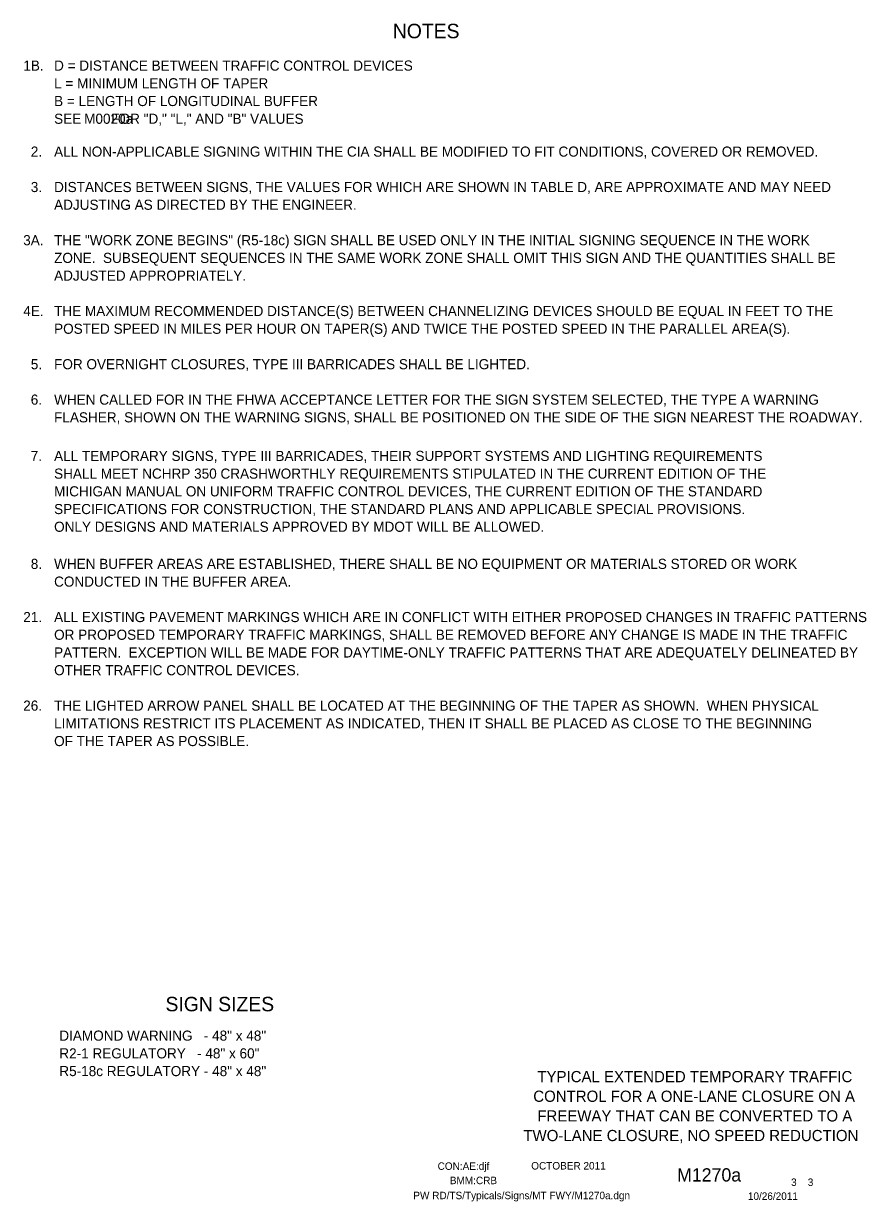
# Model space of a CAD drawing. Extents: x 16794 to 19504, y 7009 to 8243.
# Drawn here: x 18805 to 19504, y 7218 to 8195 of the extents above; entities that cross this region are included whole.
import ezdxf

# ---------------------------------------------------------------- set-up
doc = ezdxf.new("R2010")
doc.units = 0
for name, color, linetype in [('BORDER', 7, 'Continuous'), ('BORDER_SIGNAL_WO', 7, 'Continuous'), ('TYPICAL_TEXT_DIMEN_PR', 7, 'Continuous')]:
    doc.layers.add(name, color=color, linetype=linetype)

msp = doc.modelspace()

# ---------------------------------------------------------------- linework, layer by layer
at = {"layer": 'BORDER'}
msp.add_line((19347.25, 7297.5), (19347.25, 7297.5), dxfattribs=at)
msp.add_line((19347.25, 7297.5), (19347.25, 7297.5), dxfattribs=at)

# ---------------------------------------------------------------- texts
for s, p in [('TYPICAL EXTENDED TEMPORARY TRAFFIC', (19231.38, 7317.03)), ('CONTROL FOR A ONE-LANE CLOSURE ON A', (19228, 7300.73)), ('FREEWAY THAT CAN BE CONVERTED TO A', (19231.33, 7284.43)), ('TWO-LANE CLOSURE, NO SPEED REDUCTION ', (19219.79, 7268.13))]:
    msp.add_text(s, height=9.3, dxfattribs=at).set_placement(p)
at = {"layer": 'BORDER_SIGNAL_WO'}
for s, height, p in [('CON:AE:djf  ', 6.2, (19148.69, 7244.31)), ('    OCTOBER 2011    ', 6.2, (19217.08, 7244.59)), ('    M1270a   ', 11, (19330.86, 7234.63)), ('BMM:CRB   ', 6.2, (19158.81, 7232.42)), (' 3    3 ', 6.2, (19439.45, 7230.95)), ('PW RD/TS/Typicals/Signs/MT FWY/M1270a.dgn      ', 6.2, (19128.55, 7219.96)), ('10/26/2011    ', 6.2, (19405.93, 7219.38))]:
    msp.add_text(s, height=height, dxfattribs=at).set_placement(p)
at = {"layer": 'TYPICAL_TEXT_DIMEN_PR'}
for s, height, p in [('NOTES', 12, (19111.55, 8183.25)), ('1B.', 8.4, (18805.19, 8156.36)), ('D = DISTANCE BETWEEN TRAFFIC CONTROL DEVICES', 8.4, (18830.7, 8156.36)), ('L = MINIMUM LENGTH OF TAPER', 8.4, (18830.7, 8141.66)), ('B = LENGTH OF LONGITUDINAL BUFFER', 8.4, (18830.7, 8126.96)), ('SEE        FOR "D," "L," AND "B" VALUES', 8.4, (18830.7, 8112.26)), ('M0020a', 8.4, (18855.62, 8112.26)), ('2.', 8.4, (18811.39, 8085)), ('ALL NON-APPLICABLE SIGNING WITHIN THE CIA SHALL BE MODIFIED TO FIT CONDITIONS, COVERED OR REMOVED.', 8.4, (18830.7, 8085)), ('3.', 8.4, (18811.39, 8055.6)), ('DISTANCES BETWEEN SIGNS, THE VALUES FOR WHICH ARE SHOWN IN TABLE D, ARE APPROXIMATE AND MAY NEED', 8.4, (18830.7, 8055.6)), ('ADJUSTING AS DIRECTED BY THE ENGINEER.', 8.4, (18830.7, 8040.9)), ('3A.', 8.4, (18805.09, 8011.49)), ('THE "WORK ZONE BEGINS" (R5-18c) SIGN SHALL BE USED ONLY IN THE INITIAL SIGNING SEQUENCE IN THE WORK', 8.4, (18830.7, 8011.49)), ('ZONE.  SUBSEQUENT SEQUENCES IN THE SAME WORK ZONE SHALL OMIT THIS SIGN AND THE QUANTITIES SHALL BE', 8.4, (18830.7, 7996.79)), ('ADJUSTED APPROPRIATELY.', 8.4, (18830.7, 7982.09)), ('4E.', 8.4, (18805.13, 7952.7)), ('THE MAXIMUM RECOMMENDED DISTANCE(S) BETWEEN CHANNELIZING DEVICES SHOULD BE EQUAL IN FEET TO THE', 8.4, (18830.7, 7952.7)), ('POSTED SPEED IN MILES PER HOUR ON TAPER(S) AND TWICE THE POSTED SPEED IN THE PARALLEL AREA(S).', 8.4, (18830.7, 7938)), ('5.', 8.4, (18811.39, 7908.6)), ('FOR OVERNIGHT CLOSURES, TYPE III BARRICADES SHALL BE LIGHTED. ', 8.4, (18830.7, 7908.6)), ('6.', 8.4, (18811.34, 7879.2)), ('WHEN CALLED FOR IN THE FHWA ACCEPTANCE LETTER FOR THE SIGN SYSTEM SELECTED, THE TYPE A WARNING ', 8.4, (18830.7, 7879.2)), ('FLASHER, SHOWN ON THE WARNING SIGNS, SHALL BE POSITIONED ON THE SIDE OF THE SIGN NEAREST THE ROADWAY.', 8.4, (18830.7, 7864.5)), ('7.', 8.4, (18811.34, 7832.48)), ('ALL TEMPORARY SIGNS, TYPE III BARRICADES, THEIR SUPPORT SYSTEMS AND LIGHTING REQUIREMENTS', 8.4, (18830.7, 7832.5)), ('SHALL MEET NCHRP 350 CRASHWORTHLY REQUIREMENTS STIPULATED IN THE CURRENT EDITION OF THE', 8.4, (18830.7, 7817.8)), ('MICHIGAN MANUAL ON UNIFORM TRAFFIC CONTROL DEVICES, THE CURRENT EDITION OF THE STANDARD', 8.4, (18830.7, 7803.1)), ('SPECIFICATIONS FOR CONSTRUCTION, THE STANDARD PLANS AND APPLICABLE SPECIAL PROVISIONS.', 8.4, (18830.7, 7788.4)), ('ONLY DESIGNS AND MATERIALS APPROVED BY MDOT WILL BE ALLOWED.', 8.4, (18830.7, 7773.7)), ('8.', 8.4, (18811.39, 7742.9)), ('WHEN BUFFER AREAS ARE ESTABLISHED, THERE SHALL BE NO EQUIPMENT OR MATERIALS STORED OR WORK     ', 8.4, (18830.7, 7742.9)), ('CONDUCTED IN THE BUFFER AREA.', 8.4, (18830.7, 7728.2)), ('21.', 8.4, (18805.14, 7698.8)), ('ALL EXISTING PAVEMENT MARKINGS WHICH ARE IN CONFLICT WITH EITHER PROPOSED CHANGES IN TRAFFIC PATTERNS', 8.4, (18830.7, 7698.8)), ('OR PROPOSED TEMPORARY TRAFFIC MARKINGS, SHALL BE REMOVED BEFORE ANY CHANGE IS MADE IN THE TRAFFIC', 8.4, (18830.7, 7684.1)), ('PATTERN.  EXCEPTION WILL BE MADE FOR DAYTIME-ONLY TRAFFIC PATTERNS THAT ARE ADEQUATELY DELINEATED BY', 8.4, (18830.7, 7669.4)), ('OTHER TRAFFIC CONTROL DEVICES.', 8.4, (18830.7, 7654.7)), ('26.', 8.4, (18805.09, 7625.3)), ('THE LIGHTED ARROW PANEL SHALL BE LOCATED AT THE BEGINNING OF THE TAPER AS SHOWN.  WHEN PHYSICAL', 8.4, (18830.7, 7625.3)), ('LIMITATIONS RESTRICT ITS PLACEMENT AS INDICATED, THEN IT SHALL BE PLACED AS CLOSE TO THE BEGINNING', 8.4, (18830.7, 7610.6)), ('OF THE TAPER AS POSSIBLE.', 8.4, (18830.7, 7595.9)), ('SIGN SIZES', 12, (18923.08, 7375.86)), ('DIAMOND WARNING   - 48" x 48"', 8.4, (18835.04, 7351.47)), ('R2-1 REGULATORY   - 48" x 60"', 8.4, (18835.04, 7336.77)), ('R5-18c REGULATORY - 48" x 48"', 8.4, (18835.04, 7322.07))]:
    msp.add_text(s, height=height, dxfattribs=at).set_placement(p)

doc.saveas('drawing.dxf')
